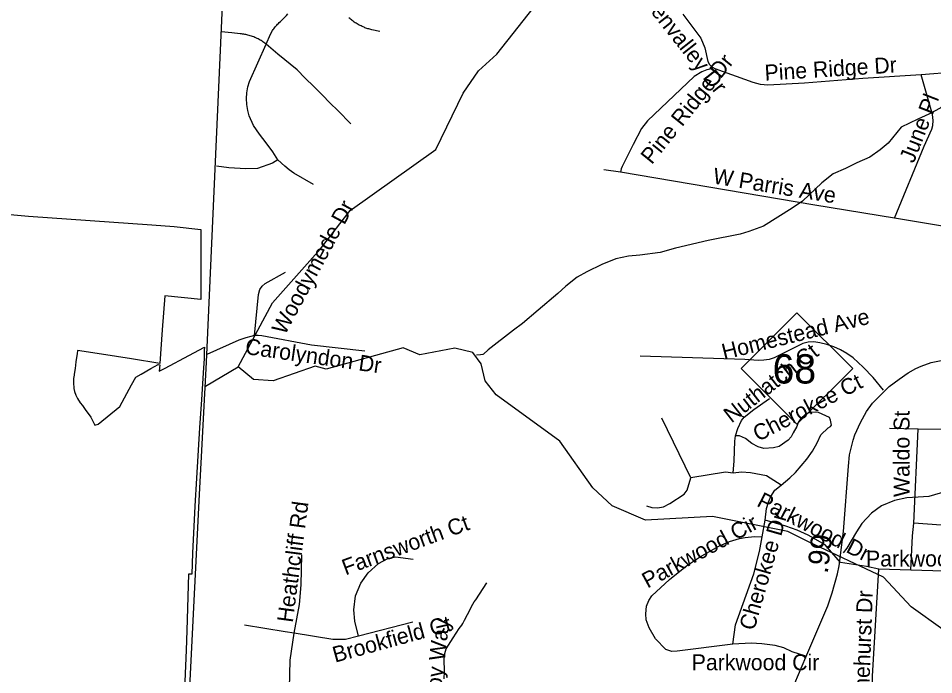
# Model space of a CAD drawing. Extents: x 1662474 to 1856135, y 779280 to 917889.
# Drawn here: x 1689866 to 1695335, y 812299 to 816221 of the extents above; entities that cross this region are included whole.
import ezdxf

# ---------------------------------------------------------------- set-up
doc = ezdxf.new("R2010")
doc.units = 0
for name, color, linetype in [('Exist Boundary Political City Limit New', 7, 'Continuous'), ('Exist Boundary Political CountyLine', 7, 'Continuous'), ('Exist Hydrographic Misc Water Feature', 7, 'Continuous'), ('Exist Road Non-System Type 51', 7, 'Continuous'), ('Exist Road Non-System Type 51 Label', 7, 'Continuous'), ('Exist Road Primary NC Service Mileage Hundredths English Label', 7, 'Continuous'), ('Exist Road Primary NC Shield CELL', 7, 'Continuous'), ('Exist Road Primary NC Shield Number Label', 7, 'Continuous'), ('Exist Road Primary NC UnDivided 4 Lane Attributed', 7, 'Continuous'), ('Map Preparation Boundary City Limit Buffer Line', 7, 'Continuous')]:
    doc.layers.add(name, color=color, linetype=linetype)

msp = doc.modelspace()

# ---------------------------------------------------------------- linework, layer by layer
at = {"layer": 'Exist Boundary Political City Limit New'}
msp.add_lwpolyline([(1689614.9, 815066.2), (1689926.1, 815039.6), (1690663.1, 814987.5), (1690797.9, 814977.1), (1690956.9, 814959.6), (1690956.2, 814935.6), (1690956.2, 814929.8), (1690956.9, 814541.4), (1690740.2, 814562.4), (1690725.8, 814358.7), (1690711.6, 814158.9), (1690541.2, 814185.8), (1690362.5, 814213.9), (1690220.1, 814236.4), (1690217.2, 814216.8), (1690215.6, 814205.7), (1690210.2, 814168.1), (1690204.6, 814129), (1690199.6, 814094.4), (1690198.8, 814088.3), (1690195.9, 814069.2), (1690194.6, 814044.4), (1690198, 814009), (1690201.9, 813991.6), (1690210.1, 813968.1), (1690219.2, 813948.9), (1690235, 813924.1), (1690248.5, 813906.4), (1690265.6, 813884), (1690281.6, 813862.2), (1690289, 813851.5), (1690298.2, 813836.8), (1690306.9, 813821.7), (1690314.9, 813806.2), (1690322.4, 813790.4), (1690343.1, 813795.7), (1690471.8, 813900.9), (1690472.5, 813902.3), (1690541.9, 814030.1), (1690567.4, 814077.1), (1690599.6, 814095.4), (1690656.5, 814127.7), (1690701.2, 814152.9), (1690711, 814151.3), (1690708.2, 814111.9), (1690742.6, 814130.2), (1690884, 814205.3), (1690977.6, 814255), (1690977, 814235.1), (1690975.4, 814186.4), (1690973.1, 814132.8), (1690959.6, 813943.2), (1690949.2, 813774.5), (1690931, 813472.1), (1690921, 813305.6), (1690907.1, 813024.8), (1690902.4, 812899.9), (1690883.4, 812899), (1690871.9, 812563.6), (1690868.2, 812444.9), (1690853.5, 812069.9)], dxfattribs=at)
at = {"layer": 'Exist Boundary Political CountyLine'}
msp.add_lwpolyline([(1690220.4, 796849.4), (1690253.3, 797643.4), (1690261, 798032.2), (1690301.7, 799178.2), (1690347.6, 800042.9), (1690382.7, 800862.5), (1690417.8, 801672.6), (1690459.9, 802612.4), (1690490.6, 803379.9), (1690531.6, 804201.7), (1690578.3, 805157.6), (1690614.8, 805955.1), (1690649.3, 806683.1), (1690688.7, 807554.8), (1690723, 808322.5), (1690748.6, 808998.5), (1690777.2, 809760.4), (1690803.1, 810502.1), (1690838, 811298), (1690892.7, 812263.6), (1690949.1, 813375.2), (1690989.8, 814167.1), (1691300.1, 821093.4)], dxfattribs=at)
at = {"layer": 'Exist Hydrographic Misc Water Feature'}
for points in [[(1691179.9, 814137.6), (1691384.8, 814520.8), (1691670.9, 814843.2), (1691848.9, 815072.6), (1692360.9, 815436.5), (1692522.9, 815774.5), (1692615.9, 815907.2), (1692725.9, 816006.7), (1692979.9, 816329.8)], [(1695531.7, 816225.4), (1695535.2, 816107.2), (1695548.8, 816011.7), (1695562.7, 815923.7), (1695544.3, 815859.1), (1695512.2, 815819.7), (1695471.8, 815775.3), (1695373.6, 815683.8), (1695305.3, 815648.2), (1695241.3, 815618.3), (1695141.1, 815571.1), (1695062.6, 815475.1), (1695014.4, 815435.8), (1694954.3, 815391.9), (1694876.1, 815358.2)], [(1694876.1, 815358.2), (1694808.1, 815324.3), (1694733.9, 815292.2), (1694667.7, 815238.5), (1694551.1, 815129.3), (1694489.2, 815087.1), (1694318.5, 814979.8), (1694230.4, 814946.3), (1694178.1, 814930.9), (1693988.2, 814893.7), (1693791.9, 814848.5), (1693701.6, 814822.4), (1693579.6, 814805.2), (1693511.6, 814799.2), (1693435.5, 814783.5), (1693353.2, 814749.9), (1693263.1, 814705.8), (1693205.2, 814674.2), (1693136.9, 814620.6), (1693088.6, 814577.2), (1692972.3, 814477), (1692877.7, 814397.7), (1692823.9, 814357.8), (1692673.4, 814240.1), (1692645.1, 814214.5), (1692641.6, 814212.9), (1692626.4, 814209.2), (1692604.2, 814207.2)], [(1697094, 812149.7), (1695630.9, 812458.4), (1695389.9, 812568.3), (1695199.9, 812703.5), (1695035, 812880.8), (1694586.9, 813093.5), (1694462.9, 813155.1), (1694012.9, 813243), (1693612.9, 813221.5), (1693413.9, 813307.7), (1693297.9, 813415.1), (1693100.9, 813694.8), (1692720.8, 813971.7), (1692654.9, 814055.1), (1692630.8, 814157.3), (1692581.9, 814224), (1692473.9, 814249.2), (1692264.9, 814210.8), (1692164.8, 814252.1), (1691704.8, 814123.7), (1691638.9, 814141.4), (1691387.9, 814054.6), (1691270.8, 814063.5), (1691179.9, 814137.6)], [(1690983.4, 814023.2), (1691179.9, 814137.6)], [(1695408.5, 813394.3), (1695306.2, 813362.8), (1695242.4, 813359.1), (1695174.2, 813355.6), (1695100.3, 813339.9), (1695024, 813307.8), (1694963.9, 813263.9), (1694905.7, 813202.7), (1694873.4, 813152.4), (1694817, 813055.1), (1694795, 813026.9)]]:
    msp.add_lwpolyline(points, dxfattribs=at)
at = {"layer": 'Exist Road Non-System Type 51'}
for p, q in [((1695530.2, 815903.4), (1695260.6, 815883.7)), ((1693464.6, 815301.2), (1693363.6, 815316.2)), ((1694201.9, 813837.5), (1694096.1, 813883.9)), ((1693884.6, 813474.5), (1693711.6, 813831.7)), ((1695242.6, 813766.6), (1695070.9, 813770.2)), ((1695216.1, 813203.4), (1695242.6, 813766.6)), ((1695603.1, 813762.9), (1695242.6, 813766.6)), ((1694309.5, 813122.5), (1694328.1, 813221.8)), ((1695543.1, 813181.6), (1695216.1, 813203.4)), ((1695199, 812923.1), (1695007.9, 812930.2)), ((1695490.6, 812913.4), (1695199, 812923.1)), ((1692222.1, 812613.1), (1691898, 812528.4))]:
    msp.add_line(p, q, dxfattribs=at)
for points in [[(1691347.4, 816066.6), (1691372.4, 816126.2), (1691385.4, 816147.7), (1691389.4, 816153.4), (1691393.4, 816159.2), (1691397.2, 816164.5), (1691401.4, 816170), (1691405.9, 816175.2), (1691410.4, 816180.5), (1691415.1, 816185.5), (1691419.9, 816190.4), (1691424.9, 816195.2), (1691431.9, 816202.2), (1691467.9, 816238.8), (1691476.8, 816247.4)], [(1693835.5, 816246.9), (1693943.9, 816103.1), (1693968.1, 816043.8), (1693986.4, 815963.9), (1693996.6, 815945.4), (1694015.9, 815926.7)], [(1692025.6, 816142.7), (1691978.1, 816153.2), (1691972, 816154.5), (1691966, 816155.9), (1691960.2, 816157.4), (1691954.1, 816158.9), (1691948.4, 816160.8), (1691942.6, 816162.9), (1691936.9, 816165), (1691931.4, 816167.4), (1691925.9, 816169.8), (1691920.4, 816172.4), (1691914.9, 816175.2), (1691908.5, 816178.1), (1691902.2, 816181), (1691895.9, 816184.4), (1691889.9, 816187.9), (1691884.1, 816191.2), (1691878.1, 816194.9), (1691872.4, 816198.9), (1691866.8, 816203.1), (1691861.2, 816207.2), (1691855.8, 816211.8), (1691850.5, 816216.2), (1691845.9, 816220.4), (1691841.4, 816224.6)], [(1691347.4, 816066.6), (1691338.4, 816072.4), (1691332.9, 816076.5), (1691327.4, 816080.5), (1691321.9, 816084.2), (1691316.4, 816087.9), (1691310.6, 816091.2), (1691304.9, 816094.7), (1691298.4, 816098.1), (1691292, 816101.2), (1691285.4, 816104.4), (1691278.9, 816107.2), (1691272.1, 816109.9), (1691265.2, 816112.2), (1691258.4, 816114.6), (1691251.6, 816116.7), (1691244.8, 816118.9), (1691237.6, 816120.4), (1691230.9, 816122.2), (1691224.6, 816123.5), (1691218.2, 816124.9), (1691212.2, 816125.9), (1691205.9, 816126.7), (1691199.6, 816127.5), (1691192.2, 816128.2), (1691142.4, 816134.2), (1691078.2, 816140.6)], [(1691415.9, 815376), (1691385.6, 815423.5), (1691345.9, 815476.9), (1691306.6, 815529.4), (1691270.5, 815581.5), (1691244.2, 815639), (1691236.1, 815670.8), (1691230.9, 815705.9), (1691229.5, 815741.1), (1691231.4, 815776.6), (1691237.1, 815810.7), (1691246.6, 815842.9), (1691347.4, 816066.6)], [(1691851.6, 815589.7), (1691773.9, 815669.5), (1691729.2, 815714.1), (1691681.8, 815762.9), (1691631.1, 815814.1), (1691580.6, 815864.2), (1691531.6, 815913), (1691417.1, 816007.8), (1691347.4, 816066.6)], [(1694015.9, 815926.7), (1694009.2, 815919.9), (1693978.9, 815912.5), (1693949.6, 815901.8), (1693904.2, 815872.6), (1693624.2, 815609.4), (1693589.9, 815561.9), (1693540.5, 815467.7), (1693474.1, 815336.4), (1693467.9, 815320.9), (1693464.6, 815301.2)], [(1695260.6, 815883.7), (1694912.4, 815860.9), (1694563.4, 815832.8), (1694343.4, 815821.7), (1694299.9, 815826.2), (1694257.4, 815836.7), (1694028.9, 815919.9), (1694015.9, 815926.7)], [(1695100.6, 815026.9), (1695278.9, 815456.4), (1695323.4, 815557.7), (1695329.4, 815580.8), (1695331.9, 815610.7), (1695327.6, 815645.9), (1695260.6, 815883.7)], [(1691415.9, 815376), (1691384.6, 815355.2), (1691295.4, 815323.9), (1691224.9, 815321.4), (1691122.9, 815326.9), (1691049.4, 815338.4)], [(1691630.2, 815228.4), (1691511.4, 815296.7), (1691484.9, 815315.9), (1691459.1, 815337.9), (1691415.9, 815376)], [(1695100.6, 815026.9), (1694624.5, 815104.4), (1693464.6, 815301.2)], [(1695672.5, 814936.4), (1695626.6, 814938.5), (1695100.6, 815026.9)], [(1691276.8, 814324.8), (1691299.9, 814570.2), (1691308.2, 814600.4), (1691322.1, 814621.4), (1691341.4, 814637.2), (1691461.9, 814703.9)], [(1691276.8, 814324.8), (1691254.5, 814320.2), (1691224.2, 814311.8), (1691182.9, 814297.1), (1690991.8, 814212.3)], [(1691935.6, 814232.8), (1691618.2, 814267.2), (1691320.4, 814324.4), (1691298, 814326.4), (1691276.8, 814324.8)], [(1695036, 813999.2), (1694972.8, 814075.2), (1694914.2, 814136.9), (1694853.4, 814192.9), (1694816.9, 814217.2), (1694778.9, 814239.1), (1694738.4, 814257.2), (1694697.1, 814271.6), (1694654.4, 814282.6), (1694618.1, 814288.1), (1694585.1, 814286.2), (1694553.1, 814277.7), (1694381.6, 814192.1), (1694352.9, 814182.4), (1694319.5, 814177.4), (1694285.9, 814176.4), (1694206.4, 814181.9), (1693580.9, 814201.5)], [(1694201.9, 813837.5), (1694259.6, 813883.9), (1694354.4, 813948.2)], [(1694423.1, 813431.4), (1694476.4, 813475), (1694510.4, 813507), (1694577.5, 813587.4), (1694610.1, 813634.9), (1694638.1, 813684.5), (1694660.6, 813731.7), (1694704, 813774), (1694718.4, 813782.1), (1694725, 813790.5), (1694723.4, 813800.5), (1694719.5, 813820.4), (1694712.6, 813835.7), (1694647.9, 813865.4), (1694629.5, 813867.9), (1694598.5, 813866.4), (1694572, 813858.5), (1694541.2, 813829.9), (1694525.5, 813806), (1694517.1, 813781.1), (1694494.9, 813744.6), (1694483.5, 813720.7), (1694466.5, 813699.2), (1694411.6, 813662.7), (1694378.2, 813654.9), (1694320.6, 813650.1), (1694286.9, 813660.1), (1694248.9, 813681.1), (1694209.8, 813709.2), (1694174.1, 813725.9), (1694151.5, 813727)], [(1694151.5, 813727), (1694164.9, 813769.5), (1694186.1, 813818.1), (1694201.9, 813837.5)], [(1694137.9, 813502.6), (1694143.4, 813576.1), (1694146.2, 813693.9), (1694151.5, 813727)], [(1694137.9, 813502.6), (1694090.9, 813509.9), (1693884.6, 813474.5)], [(1694423.1, 813431.4), (1694336, 813486.4), (1694240.2, 813505.8), (1694187.8, 813508.9), (1694137.9, 813502.6)], [(1693620, 813308.1), (1693650.2, 813297.6), (1693685.6, 813295.2), (1693720, 813302.6), (1693758.6, 813321.2), (1693844.1, 813377.7), (1693862.2, 813401.5), (1693884.6, 813474.5)], [(1694328.1, 813221.8), (1694336, 813291), (1694347.4, 813330.4), (1694362.9, 813364), (1694385.1, 813400.5), (1694423.1, 813431.4)], [(1694779.1, 812970), (1694686.6, 813074.5), (1694584.4, 813131.8), (1694519, 813161.7), (1694452.6, 813185.8), (1694328.1, 813221.8)], [(1695199, 812923.1), (1695208.1, 813128.4), (1695216.1, 813203.4)], [(1694134.8, 812481.4), (1693801.6, 812439.6), (1693770.1, 812437.5), (1693734.1, 812450.1), (1693673.4, 812512.9), (1693634.5, 812579.5), (1693617.4, 812626.5), (1693615.1, 812663.2), (1693619.8, 812708.4), (1693633.1, 812742.8), (1693651.2, 812769), (1693755.8, 812866.9), (1693857.9, 812948.5), (1693936.6, 813001), (1694051.2, 813066.6), (1694115.6, 813094.8), (1694173.9, 813112.9), (1694208.8, 813119.4), (1694263.9, 813124.1), (1694309.5, 813122.5)], [(1694134.8, 812481.4), (1694151.8, 812595.8), (1694260.6, 812900.5), (1694294.6, 813034.1), (1694309.5, 813122.5)], [(1691514.9, 812547.5), (1691545, 812718.1), (1691556.6, 812834.9), (1691559.4, 813014.4)], [(1691898, 812528.4), (1691877.2, 812618.1), (1691869.9, 812686.1), (1691880.4, 812770.4), (1691912.8, 812846.4), (1691955.8, 812906.8), (1692018, 812962.9), (1692068.9, 812991), (1692120.1, 813002.6), (1692225.4, 812989.8)], [(1695007.9, 812930.2), (1694934.1, 812944.6), (1694779.1, 812970)], [(1695018.4, 811922), (1694979.9, 812110.5), (1694972.5, 812192.7), (1694969.9, 812290.8), (1695007.9, 812930.2)], [(1692410.9, 812274), (1692412.4, 812318.4), (1692410.6, 812390.8), (1692411.6, 812408.7), (1692414.2, 812425.7), (1692417.6, 812439.9), (1692422.1, 812453.8), (1692463.1, 812519.7), (1692500.6, 812574.2), (1692508.5, 812583.9), (1692515.9, 812593.9), (1692522.6, 812605.2), (1692528.4, 812616.8), (1692531.9, 812624.9), (1692567.4, 812691.4), (1692573.6, 812706), (1692581.5, 812719.7), (1692590.4, 812733.4), (1692600.1, 812746.7), (1692665.1, 812847.8)], [(1691514.9, 812547.5), (1691460.5, 812554.6), (1691218, 812595.2)], [(1691500.1, 811843.6), (1691483.6, 811975.4), (1691484.6, 812131.5), (1691489.6, 812385), (1691514.9, 812547.5)], [(1691898, 812528.4), (1691820.1, 812508.9), (1691745, 812508.9), (1691514.9, 812547.5)], [(1694572, 812408.4), (1694489.9, 812434.4), (1694439.4, 812460.1), (1694388.8, 812472.4), (1694307.6, 812483.7), (1694243.9, 812487.1), (1694134.8, 812481.4)]]:
    msp.add_lwpolyline(points, dxfattribs=at)
at = {"layer": 'Exist Road Primary NC Shield CELL'}
msp.add_lwpolyline([(1694185.1, 814128.4), (1694518.1, 814461.4), (1694851.1, 814128.4), (1694518.1, 813795.4)], close=True, dxfattribs=at)
at = {"layer": 'Exist Road Primary NC UnDivided 4 Lane Attributed'}
msp.add_lwpolyline([(1694506.2, 812248.6), (1694571.8, 812402.9), (1694667.2, 812626.1), (1694701.8, 812710.5), (1694728.2, 812788), (1694760.7, 812901.9), (1694770.7, 812949.5), (1694795.8, 813155), (1694825.3, 813543.8), (1694832.1, 813612), (1694853.4, 813700.6), (1694864.5, 813731.3), (1694897.7, 813806.3), (1694933.2, 813871.1), (1694969.7, 813920.4), (1695005.2, 813956.2), (1695068.6, 814020.1), (1695129.1, 814065.3), (1695183.6, 814102.8), (1695228.2, 814127.6), (1695260.4, 814142.6), (1695320.8, 814163.3), (1695390.2, 814178.6)], dxfattribs=at)
at = {"layer": 'Map Preparation Boundary City Limit Buffer Line'}
msp.add_lwpolyline([(1689614.9, 815066.2), (1689926.1, 815039.6), (1690663.1, 814987.5), (1690797.9, 814977.1), (1690956.9, 814959.6), (1690956.2, 814935.6), (1690956.2, 814929.8), (1690956.9, 814541.4), (1690740.2, 814562.4), (1690725.8, 814358.7), (1690711.6, 814158.9), (1690541.2, 814185.8), (1690362.5, 814213.9), (1690220.1, 814236.4), (1690217.2, 814216.8), (1690215.6, 814205.7), (1690210.2, 814168.1), (1690204.6, 814129), (1690199.6, 814094.4), (1690198.8, 814088.3), (1690195.9, 814069.2), (1690194.6, 814044.4), (1690198, 814009), (1690201.9, 813991.6), (1690210.1, 813968.1), (1690219.2, 813948.9), (1690235, 813924.1), (1690248.5, 813906.4), (1690265.6, 813884), (1690281.6, 813862.2), (1690289, 813851.5), (1690298.2, 813836.8), (1690306.9, 813821.7), (1690314.9, 813806.2), (1690322.4, 813790.4), (1690343.1, 813795.7), (1690471.8, 813900.9), (1690472.5, 813902.3), (1690541.9, 814030.1), (1690567.4, 814077.1), (1690599.6, 814095.4), (1690656.5, 814127.7), (1690701.2, 814152.9), (1690711, 814151.3), (1690708.2, 814111.9), (1690742.6, 814130.2), (1690884, 814205.3), (1690977.6, 814255), (1690977, 814235.1), (1690975.4, 814186.4), (1690973.1, 814132.8), (1690959.6, 813943.2), (1690949.2, 813774.5), (1690931, 813472.1), (1690921, 813305.6), (1690907.1, 813024.8), (1690902.4, 812899.9), (1690883.4, 812899), (1690871.9, 812563.6), (1690868.2, 812444.9), (1690853.5, 812069.9)], dxfattribs=at)

# ---------------------------------------------------------------- texts
at = {"layer": 'Exist Road Non-System Type 51 Label'}
for s, rotation, p in [('Greenvalley Dr', 308.2744, (1693509.5, 816426.5)), ('Pine Ridge Dr', 51.2524, (1693650.5, 815343.3)), ('Pine Ridge Dr', 3.5375, (1694327.6, 815848.4)), ('June Pl', 68.7383, (1695216, 815350.7)), ('W Parris Ave', 350.6992, (1694011.9, 815234.6)), ('Woodymede Dr', 61.7018, (1691458.7, 814323.3)), ('Homestead Ave', 13.9245, (1694082.3, 814179.8)), ('Carolyndon Dr', 351.8025, (1691216.8, 814215.5)), ('Nuthatch Ct', 37.8907, (1694126.9, 813798.9)), ('Cherokee Ct', 27.4377, (1694286.1, 813689.4)), ('Waldo St', 90, (1695191, 813360.3)), ('Parkwood Dr', 332.6872, (1694272.1, 813309.2)), ('Heathcliff Rd', 82.537, (1691505.4, 812606.9)), ('Farnsworth Ct', 20.2257, (1691820.7, 812891.6)), ('Parkwood Cir', 28.5798, (1693625.2, 812812.3)), ('Cherokee Dr', 74.0986, (1694262.6, 812558)), ('Pinehurst Dr', 87.9331, (1694946.2, 812094.1)), ('Brookfield Ct', 15.3699, (1691758.2, 812370)), ('Dunloy Way', 83.4608, (1692364.3, 811949))]:
    msp.add_text(s, height=95, rotation=rotation, dxfattribs=at).set_placement(p)
for s, p in [('Parkwood Dr', (1694930.9, 812945)), ('Parkwood Cir', (1693889.5, 812325.1))]:
    msp.add_text(s, height=95, dxfattribs=at).set_placement(p)
at = {"layer": 'Exist Road Primary NC Service Mileage Hundredths English Label'}
msp.add_text('.99', height=125, rotation=83.0426, dxfattribs=at).set_placement((1694701.6, 812899.4))
at = {"layer": 'Exist Road Primary NC Shield Number Label'}
msp.add_text('68', height=175, dxfattribs=at).set_placement((1694372.3, 814038.6))

doc.saveas('drawing.dxf')
